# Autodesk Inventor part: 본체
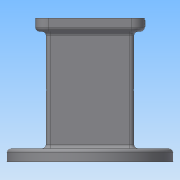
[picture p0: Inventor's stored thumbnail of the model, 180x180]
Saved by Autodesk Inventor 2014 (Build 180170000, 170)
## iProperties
Created: 2018-10
Part Number: 본체
Material: Generic
Document SubType Name: Modeling
Designer: Administrator
Density: 1 g/cm^3
Appearance: Default
Author: Administrator
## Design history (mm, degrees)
sketch "스케치1"
  geometry: L1 (-37, 33)-(37, 33); L2 (37, 33)-(37, -33); L3 (37, -33)-(-37, -33); L4 (-37, -33)-(-37, 33); 1 further point
  constraints: 8 end point, 2 parallel, 1 horizontal, 1 perpendicular
  dimensions: "d0" = 74 distance of L1.start L1.end; "d1" = 66 distance of L1.end L2.end; "d2" = 33 distance from line of point (0, 0) L1; "d3" = 37 distance from line of point (0, 0) L4
extrude "돌출1" new body sketch "스케치1" stored distance "d4" = 108; taper "d5" = 0 deg
sketch "스케치2"
  geometry: L1 (-37, -33)-(37, -33) reference; L2 (37, -33)-(37, 33) reference; L3 (37, 33)-(-37, 33) reference; L4 (-37, 33)-(-37, -33) reference; L5 (-46, 41)-(46, 41); L6 (46, 41)-(46, -41); L7 (46, -41)-(-46, -41); L8 (-46, -41)-(-46, 41); 1 further point
  constraints: 8 end point, 2 parallel, 1 horizontal, 1 perpendicular
  dimensions: "d6" = 92 distance of L5.start L5.end; "d7" = 82 distance of L5.end L6.end; "d8" = 41 distance from line of point (0, 0) L5; "d9" = 46 distance from line of point (0, 0) L8
extrude "돌출2" join sketch "스케치2" distance "d10" = 10; taper "d11" = 0 deg
sketch "스케치3"
  geometry: L1 (37, 33)-(-37, 33) reference; L2 (-37, 33)-(-37, -33) reference; L3 (-37, -33)-(37, -33) reference; L4 (37, -33)-(37, 33) reference; C1 r 62.5 at (0, 0); 1 further point
  constraints: 1 centre point, 1 coincident
  dimensions: "d12" = 125 diameter of C1
extrude "돌출3" join sketch "스케치3" distance "d13" = 10; taper "d14" = 0 deg
sketch "스케치4" dims "d15" = 100
  geometry: C1 r 62.5 at (0, 0) reference; 2 further points
  constraints: 1 coincident, 1 horizontal alignment, 2 other
  dimensions: "d16" = 0 vertical distance of C1.centre point (-50, 0)
hole "구멍1" sketch "스케치4" at (-50, 0) diameter "d17" = 9; stored, may be unused: countersink angle "d21" = 90 deg, drill point angle "d23" = 118 deg; dims "d18" = 6, "d19" = 4, "d20" = 2, "d22" = 10
sketch "스케치5"
  geometry: L1 (62.5, -54)-(-62.5, -54) reference; L2 (0, -54)-(0, 0); L3 (-28, -54)-(-24.826, -36); L4 (-24.826, -36)-(0, -36); L5 (-28, -54)-(0, -54)
  constraints: 8 end point, 3 perpendicular, 2 point on line, 1 midpoint
  dimensions: "d27" = 56 diameter of L3.start L2; "d28" = 18 distance between parallel lines of L1 L4; "d29" = 80 deg angle of L1 L3
revolve "회전1" sketch "스케치5" stored, may be unused: angle "d30" = 90 deg
sketch "스케치7"
  geometry: L1 (99.5, -98)-(-25.5, -98) reference; C1 r 35 at (37, -44); 1 further point
  constraints: 1 centre point
  dimensions: "d33" = 70 diameter of C1; "d34" = 54 distance from line of L1 C1.centre; "d35" = 0 distance of point (37, -44) C1.centre
extrude "돌출4" cut sketch "스케치7" distance "d36" = 3; taper "d37" = 0 deg
sketch "스케치8"
  geometry: C1 r 35 at (0, 0) reference; C2 r 24 at (0, 0)
  constraints: 1 centre point, 1 coincident
  dimensions: "d38" = 48 diameter of C2
extrude "돌출5" cut sketch "스케치8" stored distance "d39" = 3; taper "d40" = 0 deg
sketch "스케치9"
  geometry: L1 (-26, 26)-(26, 26); L2 (26, 26)-(26, -26); L3 (26, -26)-(-26, -26); L4 (-26, -26)-(-26, 26); 1 further point
  constraints: 8 end point, 2 parallel, 1 horizontal, 1 perpendicular
  dimensions: "d41" = 52 distance of L1.start L1.end; "d42" = 52 distance of L1.end L2.end; "d43" = 26 distance from line of point (0, 0) L1; "d44" = 26 distance from line of point (0, 0) L4
extrude "돌출6" cut sketch "스케치9" distance "d45" = 8; taper "d46" = 0 deg
sketch "스케치10"
  geometry: L1 (-22, 22)-(22, 22); L2 (22, 22)-(22, -22); L3 (22, -22)-(-22, -22); L4 (-22, -22)-(-22, 22); 1 further point
  constraints: 8 end point, 2 parallel, 1 horizontal, 1 perpendicular
  dimensions: "d47" = 44 distance of L1.start L1.end; "d48" = 44 distance of L1.end L2.end; "d49" = 22 distance from line of point (0, 0) L1; "d50" = 22 distance from line of point (0, 0) L4
extrude "돌출7" cut sketch "스케치10" distance "d51" = 82; taper "d52" = 0 deg
sketch "스케치11"
  geometry: L1 (95.5, -98)-(-29.5, -98) reference; 3 further points
  dimensions: "d54" = 37 distance from line of L1 point (33, -61); "d55" = 43 distance of point (33, -61) point (33, -18); "d56" = 0 horizontal distance of point (33, -44) point (33, -18); "d57" = 0 horizontal distance of point (33, -44) point (33, -61)
hole "구멍2" sketch "스케치11" at (33, -18), (33, -61) diameter "d58" = 4.134; stored, may be unused: countersink angle "d62" = 90 deg, drill point angle "d64" = 118 deg; dims "d59" = 6, "d60" = 4, "d61" = 2, "d63" = 30
sketch "스케치12"
  geometry: C1 r 24 at (0, 0) reference; 1 further point
  dimensions: "d65" = 29 distance of C1.centre point (0, 29); "d66" = 0 horizontal distance of C1.centre point (0, 29)
hole "구멍3" sketch "스케치12" at (0, 29) diameter "d67" = 3.242; stored, may be unused: countersink angle "d71" = 82 deg, drill point angle "d73" = 118 deg; dims "d68" = 4, "d69" = 3.023, "d70" = 2, "d72" = 6
fillet "모깎기1" dims "d77" = 10
sketch "스케치13"
  geometry: A1 r 10 centre (-36, 31) between (-36, 41) and (-46, 31) reference; A2 r 10 centre (-36, -31) between (-46, -31) and (-36, -41) reference; A3 r 10 centre (36, -31) between (36, -41) and (46, -31) reference; A4 r 10 centre (36, 31) between (46, 31) and (36, 41) reference; 5 further points
  constraints: 4 coincident
hole "구멍4" sketch "스케치13" at (-36, 31), (36, 31), (-36, -31), (36, -31) diameter "d78" = 3.242; stored, may be unused: countersink angle "d82" = 82 deg, drill point angle "d84" = 118 deg; dims "d79" = 4, "d80" = 3.023, "d81" = 2, "d83" = 6
fillet "모깎기2" dims "d85" = 3
fillet "모깎기3" dims "d86" = 3
fillet "모깎기4" dims "d87" = 3
fillet "모깎기5" dims "d88" = 3
fillet "모깎기6" dims "d89" = 3
fillet "모깎기7" dims "d90" = 3
fillet "모깎기8" dims "d91" = 3
chamfer "모따기1" distance "d92" = 1; stored, may be unused: second distance "d93" = 2, angle "d94" = 45 deg
fillet "모깎기9" dims "d95" = 3
sketch "스케치14"
  geometry: L1 (72, 0)-(0, 0) reference; L2 (-10, 0)-(-10, -7) reference; 2 further points
  constraints: 1 other
  dimensions: "d96" = 4 distance from line of L1 point (36, -4); "d97" = 46 distance from line of point (36, -4) L2
feature "엠보싱1" sketch "스케치14" dims "d0" = 74, "d1" = 66, "d2" = 33, "d3" = 37, "d98" = 0.5, "d99" = 0
node "솔리드1"
pattern_circular "원형 패턴1" dims angle "d25" = 360 deg
mirror "대칭1"
pattern_circular "원형 패턴2" dims angle "d75" = 360 deg
mirror "대칭2"
